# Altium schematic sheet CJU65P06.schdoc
size 127 x 101 mm
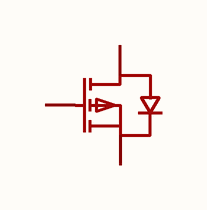
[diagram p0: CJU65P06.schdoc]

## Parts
Q?  cju65p06  [TO-252-2_L6.6-W6.1-P4.57-LS9.9-BR-CW]  (value not drawn)

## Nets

Not connected (* = marked no-connect by the designer): Q? 1(G) 2(D) 3(S)

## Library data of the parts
Q? = cju65p06: 数量:1个P沟道;漏源电压(Vdss):60V;连续漏极电流(Id):65A;导通电阻(RDS(on)):18mΩ@10V;耗散功率(Pd):120W;阈值电压(Vgs(th)):3V;; Manufacturer: CJ(江苏长电/长晶); AddInBom: yes; ModelId: ce57f84d66384067af8a68020b6de06d; ModelName: TO-252-2L-3P_L6.6-W6.1-H2.3-LS10.1-P4.6; ModelTransform: 259.842,390.52442,0,90,0,0,-39.39,0,0; Number: 1个P沟道; Drain to Source Voltage: 60V; Current - Continuous Drain(Id): 65A; Pd - Power Dissipation: 120W; Gate Threshold Voltage (Vgs(th)): 3V; Gate Charge(Qg): 152nC@10V; Input Capacitance(Ciss): 9.5nF; Reverse Transfer Capacitance (Crss@Vds): 480pF; Type: P沟道; Output Capacitance(Coss): 980pF; Vgs: ±20V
